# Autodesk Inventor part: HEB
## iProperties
Author: Jan-Steinar
Shininess: 20.0
PropertySet Name: _Private Model Information
Created: 2001-01
Part Number: HEB
Document SubType Name: Modeling
Designer: Jan-Steinar
Control State: 0
Master: False
Checked Out: False
PropertySet Name: Design Tracking Control
Density: 0.0
Volumn: 0.0
Area: 0.0
PropertySet Name: Model Information
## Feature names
1. Extrusion1
